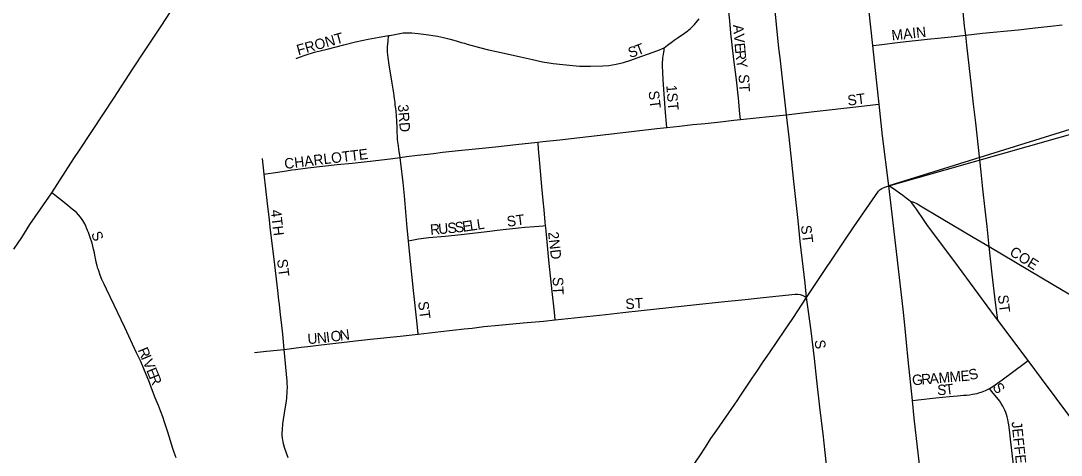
# Model space of a CAD drawing. Extents: x 1772825 to 1773716, y 1138558 to 1139032.
# Drawn here: x 1773337.37 to 1773356.3, y 1138861.97 to 1138869.86 of the extents above; entities that cross this region are included whole.
import ezdxf

# ---------------------------------------------------------------- set-up
doc = ezdxf.new("R2010")
doc.units = 0
for name, color, linetype in [('Default', 7, 'Continuous'), ('GM_X_City_Street', 7, 'Continuous'), ('GM_X_City_Street_Text', 7, 'Continuous'), ('GM_X_State_Route', 7, 'Continuous'), ('SH_Text', 7, 'Continuous')]:
    doc.layers.add(name, color=color, linetype=linetype)

msp = doc.modelspace()

# ---------------------------------------------------------------- linework, layer by layer
at = {"layer": 'Default'}
msp.add_lwpolyline([(1773353.166, 1138866.864), (1773353.051, 1138867.771), (1773352.988, 1138868.345), (1773352.939, 1138868.791), (1773352.873, 1138869.411), (1773352.801, 1138870.079), (1773352.718, 1138870.795), (1773352.633, 1138871.579), (1773352.571, 1138872.151), (1773352.507, 1138872.699), (1773352.374, 1138873.925), (1773352.299, 1138874.578), (1773352.18, 1138875.654), (1773352.138, 1138876.039), (1773352.067, 1138876.669), (1773351.996, 1138877.306)], dxfattribs=at)
at = {"layer": 'GM_X_City_Street'}
for points in [[(1773351.305, 1138868.153), (1773351.299, 1138868.204), (1773351.244, 1138868.698), (1773351.188, 1138869.19), (1773351.167, 1138869.362), (1773351.077, 1138870.226), (1773351.02, 1138870.738), (1773350.917, 1138871.684), (1773350.873, 1138872.052)], [(1773354.565, 1138869.601), (1773354.546, 1138869.763), (1773354.516, 1138870.026), (1773354.442, 1138870.621), (1773354.343, 1138871.551)], [(1773350.466, 1138868.065), (1773350.456, 1138868.17), (1773350.428, 1138868.453), (1773350.391, 1138868.786), (1773350.348, 1138869.157), (1773350.293, 1138869.639), (1773350.272, 1138869.862), (1773350.237, 1138870.195), (1773350.218, 1138870.405), (1773350.194, 1138870.581), (1773350.173, 1138870.711), (1773350.153, 1138870.801), (1773350.128, 1138870.873), (1773350.108, 1138870.918), (1773350.06, 1138871.021)], [(1773349.075, 1138869.371), (1773349.138, 1138869.419), (1773349.229, 1138869.487), (1773349.262, 1138869.51), (1773349.335, 1138869.56), (1773349.447, 1138869.638), (1773349.507, 1138869.682), (1773349.527, 1138869.698), (1773349.554, 1138869.72), (1773349.577, 1138869.742), (1773349.609, 1138869.773), (1773349.629, 1138869.796), (1773349.716, 1138869.9)], [(1773354.565, 1138869.601), (1773354.871, 1138869.634), (1773355.519, 1138869.699), (1773355.883, 1138869.74), (1773356.108, 1138869.765), (1773356.318, 1138869.787)], [(1773342.378, 1138869.179), (1773342.393, 1138869.183), (1773342.401, 1138869.185), (1773342.422, 1138869.193), (1773342.562, 1138869.243), (1773342.716, 1138869.289), (1773342.944, 1138869.347), (1773343.245, 1138869.423), (1773343.462, 1138869.479), (1773343.693, 1138869.528), (1773343.888, 1138869.565), (1773344.06, 1138869.592)], [(1773344.272, 1138867.378), (1773344.249, 1138867.528), (1773344.24, 1138867.589), (1773344.231, 1138867.661), (1773344.226, 1138867.711), (1773344.223, 1138867.758), (1773344.219, 1138867.832), (1773344.216, 1138867.918), (1773344.212, 1138868.043), (1773344.207, 1138868.129), (1773344.199, 1138868.228), (1773344.195, 1138868.265), (1773344.185, 1138868.326), (1773344.18, 1138868.376), (1773344.171, 1138868.449), (1773344.166, 1138868.492), (1773344.157, 1138868.555), (1773344.146, 1138868.619), (1773344.129, 1138868.729), (1773344.073, 1138869.06), (1773344.052, 1138869.194), (1773344.046, 1138869.243), (1773344.043, 1138869.289), (1773344.042, 1138869.326), (1773344.042, 1138869.362), (1773344.043, 1138869.397), (1773344.047, 1138869.434), (1773344.054, 1138869.489), (1773344.057, 1138869.527), (1773344.059, 1138869.553), (1773344.06, 1138869.592)], [(1773344.06, 1138869.592), (1773344.084, 1138869.596), (1773344.266, 1138869.631), (1773344.326, 1138869.641), (1773344.375, 1138869.645), (1773344.487, 1138869.642), (1773344.598, 1138869.633), (1773344.746, 1138869.613), (1773344.954, 1138869.582), (1773345.063, 1138869.56), (1773345.183, 1138869.53), (1773345.29, 1138869.499), (1773345.384, 1138869.469), (1773345.443, 1138869.453), (1773345.49, 1138869.439), (1773345.714, 1138869.377), (1773345.881, 1138869.335), (1773346.026, 1138869.302), (1773346.22, 1138869.259), (1773346.463, 1138869.207), (1773346.681, 1138869.156), (1773346.863, 1138869.118), (1773347.059, 1138869.086), (1773347.231, 1138869.065), (1773347.538, 1138869.039), (1773347.637, 1138869.034), (1773347.736, 1138869.034), (1773347.96, 1138869.041), (1773348.071, 1138869.051), (1773348.206, 1138869.071), (1773348.339, 1138869.104), (1773348.468, 1138869.148), (1773348.584, 1138869.191), (1773348.877, 1138869.292), (1773348.994, 1138869.334), (1773349.05, 1138869.358), (1773349.075, 1138869.371)], [(1773352.873, 1138869.411), (1773352.993, 1138869.425), (1773353.375, 1138869.471), (1773353.872, 1138869.527), (1773354.117, 1138869.552), (1773354.302, 1138869.572), (1773354.565, 1138869.601)], [(1773354.992, 1138865.759), (1773354.953, 1138866.124), (1773354.919, 1138866.429), (1773354.875, 1138866.806), (1773354.845, 1138867.112), (1773354.795, 1138867.557), (1773354.747, 1138868.007), (1773354.705, 1138868.349), (1773354.668, 1138868.682), (1773354.586, 1138869.416), (1773354.565, 1138869.601)], [(1773349.127, 1138867.925), (1773349.122, 1138867.991), (1773349.104, 1138868.195), (1773349.059, 1138868.78), (1773349.051, 1138868.931), (1773349.049, 1138869.028), (1773349.049, 1138869.056), (1773349.05, 1138869.118), (1773349.051, 1138869.144), (1773349.054, 1138869.196), (1773349.057, 1138869.217), (1773349.071, 1138869.289), (1773349.076, 1138869.321), (1773349.077, 1138869.328), (1773349.078, 1138869.333), (1773349.078, 1138869.336), (1773349.078, 1138869.342), (1773349.078, 1138869.347), (1773349.078, 1138869.354), (1773349.077, 1138869.36), (1773349.075, 1138869.371)], [(1773351.305, 1138868.153), (1773351.597, 1138868.187), (1773351.864, 1138868.22), (1773352.568, 1138868.298), (1773352.927, 1138868.338), (1773352.988, 1138868.345)], [(1773349.127, 1138867.925), (1773349.359, 1138867.948), (1773349.599, 1138867.974), (1773349.822, 1138867.996), (1773350.1, 1138868.023), (1773350.343, 1138868.053), (1773350.466, 1138868.065)], [(1773350.466, 1138868.065), (1773350.926, 1138868.114), (1773351.302, 1138868.153), (1773351.305, 1138868.153)], [(1773351.67, 1138864.831), (1773351.641, 1138865.091), (1773351.553, 1138865.849), (1773351.514, 1138866.233), (1773351.44, 1138866.941), (1773351.402, 1138867.294), (1773351.351, 1138867.744), (1773351.305, 1138868.153)], [(1773346.781, 1138867.656), (1773346.871, 1138867.665), (1773347.181, 1138867.698), (1773347.541, 1138867.738), (1773348.174, 1138867.816), (1773348.941, 1138867.902), (1773349.127, 1138867.925)], [(1773344.272, 1138867.378), (1773344.386, 1138867.396), (1773344.59, 1138867.419), (1773344.772, 1138867.439), (1773344.877, 1138867.452), (1773345.042, 1138867.471), (1773345.332, 1138867.504), (1773345.641, 1138867.535), (1773346.007, 1138867.572), (1773346.378, 1138867.615), (1773346.781, 1138867.656)], [(1773346.919, 1138866.141), (1773346.913, 1138866.203), (1773346.893, 1138866.425), (1773346.876, 1138866.596), (1773346.852, 1138866.849), (1773346.8, 1138867.408), (1773346.796, 1138867.454), (1773346.783, 1138867.631), (1773346.781, 1138867.656)], [(1773341.798, 1138867.074), (1773341.766, 1138867.356)], [(1773341.798, 1138867.074), (1773341.828, 1138867.078), (1773342.004, 1138867.106), (1773342.205, 1138867.136), (1773342.302, 1138867.152), (1773342.37, 1138867.161), (1773342.594, 1138867.187), (1773343.126, 1138867.247), (1773343.398, 1138867.276), (1773343.78, 1138867.316), (1773344.138, 1138867.358), (1773344.272, 1138867.378)], [(1773344.423, 1138865.865), (1773344.399, 1138866.097), (1773344.353, 1138866.678), (1773344.33, 1138866.923), (1773344.288, 1138867.272), (1773344.272, 1138867.378)], [(1773342.161, 1138863.889), (1773342.136, 1138864.164), (1773342.111, 1138864.377), (1773342.098, 1138864.516), (1773342.077, 1138864.705), (1773342.067, 1138864.783), (1773342.049, 1138864.959), (1773341.994, 1138865.427), (1773341.909, 1138866.113), (1773341.892, 1138866.243), (1773341.859, 1138866.539), (1773341.798, 1138867.074)], [(1773351.67, 1138864.831), (1773351.804, 1138865.033), (1773352.34, 1138865.84), (1773352.528, 1138866.119), (1773352.814, 1138866.526), (1773352.978, 1138866.765), (1773353.007, 1138866.793), (1773353.038, 1138866.814), (1773353.091, 1138866.84), (1773353.166, 1138866.864)], [(1773340.194, 1138861.916), (1773340.16, 1138862.015), (1773340.137, 1138862.088), (1773340.045, 1138862.386), (1773339.987, 1138862.567), (1773339.956, 1138862.662), (1773339.913, 1138862.772), (1773339.875, 1138862.867), (1773339.851, 1138862.925), (1773339.817, 1138863.012), (1773339.748, 1138863.185), (1773339.711, 1138863.286), (1773339.609, 1138863.537), (1773339.552, 1138863.668), (1773339.473, 1138863.83), (1773339.261, 1138864.289), (1773339.071, 1138864.695), (1773338.927, 1138864.984), (1773338.884, 1138865.073), (1773338.846, 1138865.159), (1773338.815, 1138865.237), (1773338.78, 1138865.333), (1773338.77, 1138865.362), (1773338.757, 1138865.409), (1773338.742, 1138865.477), (1773338.732, 1138865.517), (1773338.722, 1138865.566), (1773338.708, 1138865.646), (1773338.693, 1138865.713), (1773338.665, 1138865.82), (1773338.624, 1138865.942), (1773338.6, 1138866.011), (1773338.584, 1138866.053), (1773338.573, 1138866.082), (1773338.554, 1138866.128), (1773338.533, 1138866.171), (1773338.498, 1138866.229), (1773338.456, 1138866.29), (1773338.416, 1138866.338), (1773338.381, 1138866.375), (1773338.353, 1138866.401), (1773338.329, 1138866.421), (1773338.305, 1138866.441), (1773338.189, 1138866.533), (1773338.074, 1138866.625), (1773338.021, 1138866.669), (1773337.96, 1138866.716), (1773337.932, 1138866.737)], [(1773353.553, 1138866.586), (1773353.602, 1138866.57), (1773353.643, 1138866.554), (1773353.673, 1138866.539), (1773353.711, 1138866.519), (1773354.117, 1138866.276), (1773354.7, 1138865.93), (1773354.992, 1138865.759)], [(1773344.423, 1138865.865), (1773344.606, 1138865.897), (1773344.748, 1138865.916), (1773344.795, 1138865.921), (1773345.091, 1138865.949), (1773345.382, 1138865.976), (1773345.906, 1138866.038), (1773346.04, 1138866.054), (1773346.427, 1138866.096), (1773346.544, 1138866.108), (1773346.718, 1138866.125), (1773346.875, 1138866.138), (1773346.919, 1138866.141)], [(1773347.095, 1138864.427), (1773347.079, 1138864.568), (1773347.037, 1138864.939), (1773346.98, 1138865.509), (1773346.95, 1138865.843), (1773346.922, 1138866.103), (1773346.919, 1138866.141)], [(1773344.603, 1138864.167), (1773344.58, 1138864.356), (1773344.516, 1138864.962), (1773344.465, 1138865.433), (1773344.431, 1138865.787), (1773344.423, 1138865.865)], [(1773354.992, 1138865.759), (1773355.473, 1138865.477), (1773356.178, 1138865.057), (1773356.947, 1138864.604), (1773356.958, 1138864.597)], [(1773355.15, 1138864.422), (1773355.11, 1138864.74), (1773355.045, 1138865.257), (1773354.992, 1138865.759)], [(1773347.095, 1138864.427), (1773348.014, 1138864.524), (1773348.323, 1138864.559), (1773348.656, 1138864.596), (1773349.668, 1138864.705), (1773350.119, 1138864.752), (1773350.551, 1138864.799), (1773350.88, 1138864.832), (1773351.462, 1138864.892), (1773351.512, 1138864.892), (1773351.554, 1138864.888), (1773351.602, 1138864.87), (1773351.638, 1138864.852), (1773351.67, 1138864.831)], [(1773349.484, 1138861.598), (1773349.533, 1138861.671), (1773349.669, 1138861.877), (1773349.725, 1138861.958), (1773349.827, 1138862.113), (1773349.929, 1138862.268), (1773350.034, 1138862.422), (1773350.365, 1138862.895), (1773350.406, 1138862.956), (1773350.458, 1138863.038), (1773350.678, 1138863.367), (1773350.763, 1138863.488), (1773350.879, 1138863.664), (1773350.992, 1138863.827), (1773351.274, 1138864.236), (1773351.42, 1138864.452), (1773351.67, 1138864.831)], [(1773352.099, 1138861.184), (1773352.07, 1138861.453), (1773352.009, 1138862.018), (1773351.973, 1138862.356), (1773351.917, 1138862.787), (1773351.856, 1138863.327), (1773351.811, 1138863.722), (1773351.752, 1138864.224), (1773351.707, 1138864.58), (1773351.67, 1138864.831)], [(1773344.603, 1138864.167), (1773345.016, 1138864.214), (1773345.436, 1138864.261), (1773345.582, 1138864.277), (1773345.794, 1138864.303), (1773346.071, 1138864.332), (1773346.513, 1138864.371), (1773346.879, 1138864.405), (1773347.095, 1138864.427)], [(1773342.161, 1138863.889), (1773342.474, 1138863.929), (1773342.592, 1138863.943), (1773342.836, 1138863.971), (1773343.046, 1138863.996), (1773343.516, 1138864.049), (1773343.735, 1138864.075), (1773344.271, 1138864.131), (1773344.603, 1138864.167)], [(1773341.621, 1138863.832), (1773341.84, 1138863.856), (1773342.161, 1138863.889)], [(1773342.234, 1138861.916), (1773342.17, 1138862.108), (1773342.15, 1138862.175), (1773342.141, 1138862.215), (1773342.137, 1138862.239), (1773342.131, 1138862.277), (1773342.128, 1138862.331), (1773342.127, 1138862.373), (1773342.129, 1138862.429), (1773342.139, 1138862.535), (1773342.182, 1138862.812), (1773342.202, 1138862.947), (1773342.21, 1138863.012), (1773342.219, 1138863.118), (1773342.221, 1138863.213), (1773342.219, 1138863.261), (1773342.216, 1138863.314), (1773342.161, 1138863.889)], [(1773354.999, 1138863.18), (1773355.06, 1138863.218), (1773355.229, 1138863.338), (1773355.627, 1138863.634), (1773355.699, 1138863.688)], [(1773353.595, 1138862.961), (1773353.698, 1138862.973), (1773354.022, 1138863.011), (1773354.145, 1138863.024), (1773354.273, 1138863.036), (1773354.418, 1138863.048), (1773354.525, 1138863.055), (1773354.579, 1138863.058), (1773354.632, 1138863.065), (1773354.69, 1138863.073), (1773354.732, 1138863.081), (1773354.774, 1138863.09), (1773354.807, 1138863.098), (1773354.866, 1138863.118), (1773354.925, 1138863.142), (1773354.999, 1138863.18)], [(1773355.459, 1138861.575), (1773355.439, 1138861.742), (1773355.381, 1138862.258), (1773355.361, 1138862.428), (1773355.348, 1138862.52), (1773355.338, 1138862.576), (1773355.33, 1138862.617), (1773355.32, 1138862.661), (1773355.309, 1138862.704), (1773355.294, 1138862.745), (1773355.279, 1138862.783), (1773355.262, 1138862.821), (1773355.243, 1138862.86), (1773355.212, 1138862.908), (1773355.184, 1138862.949), (1773355.042, 1138863.127), (1773354.999, 1138863.18)]]:
    msp.add_lwpolyline(points, dxfattribs=at)
at = {"layer": 'GM_X_State_Route'}
for points in [[(1773353.166, 1138866.864), (1773353.051, 1138867.771), (1773352.988, 1138868.345), (1773352.939, 1138868.791), (1773352.873, 1138869.411), (1773352.801, 1138870.079), (1773352.718, 1138870.795), (1773352.633, 1138871.579), (1773352.571, 1138872.151), (1773352.56, 1138872.249), (1773352.507, 1138872.699), (1773352.374, 1138873.925)], [(1773337.243, 1138865.71), (1773337.386, 1138865.926), (1773337.536, 1138866.157), (1773337.726, 1138866.44), (1773337.932, 1138866.737), (1773338.278, 1138867.271), (1773338.359, 1138867.394), (1773338.41, 1138867.471), (1773338.672, 1138867.868), (1773338.863, 1138868.153), (1773339.063, 1138868.456), (1773339.406, 1138868.987), (1773339.632, 1138869.325), (1773339.765, 1138869.527), (1773339.921, 1138869.764), (1773340.093, 1138870.023), (1773340.258, 1138870.284), (1773340.327, 1138870.4), (1773340.379, 1138870.487)], [(1773358.016, 1138860.614), (1773357.968, 1138860.678), (1773357.202, 1138861.681), (1773356.814, 1138862.201), (1773356.481, 1138862.648), (1773355.942, 1138863.36), (1773355.699, 1138863.688), (1773355.15, 1138864.422), (1773355.11, 1138864.476), (1773354.35, 1138865.506), (1773353.872, 1138866.139), (1773353.808, 1138866.229), (1773353.668, 1138866.436), (1773353.635, 1138866.486), (1773353.604, 1138866.528), (1773353.579, 1138866.558), (1773353.556, 1138866.583), (1773353.553, 1138866.586), (1773353.484, 1138866.639), (1773353.423, 1138866.684), (1773353.362, 1138866.728), (1773353.293, 1138866.777), (1773353.233, 1138866.818), (1773353.166, 1138866.864)], [(1773353.456, 1138864.329), (1773353.427, 1138864.62), (1773353.225, 1138866.348), (1773353.166, 1138866.864)], [(1773353.949, 1138859.761), (1773353.934, 1138859.896), (1773353.839, 1138860.775), (1773353.77, 1138861.399), (1773353.743, 1138861.637), (1773353.628, 1138862.637), (1773353.595, 1138862.961), (1773353.519, 1138863.702), (1773353.456, 1138864.329)]]:
    msp.add_lwpolyline(points, dxfattribs=at)
at = {"layer": 'SH_Text'}
msp.add_lwpolyline([(1773543.413, 1138925.808), (1773353.166, 1138866.864), (1773543.413, 1138920.862)], close=True, dxfattribs=at)

# ---------------------------------------------------------------- texts
at = {"layer": 'GM_X_City_Street_Text'}
for s, height, rotation, p in [('A', 0.189, 274.5513, (1773350.331, 1138869.786)), ('MAIN', 0.1894, 6.1729, (1773353.225, 1138869.502)), ('FRONT', 0.1894, 15.7855, (1773342.419, 1138869.234)), ('V', 0.189, 274.5754, (1773350.345, 1138869.62)), ('S', 0.189, 17.5105, (1773348.454, 1138869.184)), ('T', 0.189, 21.2091, (1773348.594, 1138869.229)), ('E', 0.189, 274.5663, (1773350.358, 1138869.453)), ('R', 0.189, 275.2807, (1773350.369, 1138869.318)), ('Y', 0.189, 279.2352, (1773350.384, 1138869.154)), ('ST', 0.1894, 273.5882, (1773350.431, 1138868.885)), ('ST', 0.1894, 277.1217, (1773348.791, 1138868.58)), ('1ST', 0.1894, 274.9673, (1773349.115, 1138868.686)), ('ST', 0.1894, 7.1217, (1773352.425, 1138868.318)), ('3RD', 0.1894, 274.4032, (1773344.231, 1138868.336)), ('CHARLOTTE', 0.1894, 6.8698, (1773342.175, 1138867.168)), ('4TH', 0.1894, 276.841, (1773341.915, 1138866.419)), ('ST', 0.1894, 7.12, (1773346.225, 1138866.118)), ('R', 0.189, 5.2274, (1773344.826, 1138865.969)), ('U', 0.189, 5.2083, (1773344.975, 1138865.982)), ('S', 0.189, 5.2073, (1773345.141, 1138865.997)), ('S', 0.189, 6.3213, (1773345.278, 1138866.01)), ('E', 0.189, 8.1133, (1773345.417, 1138866.025)), ('L', 0.189, 8.4264, (1773345.55, 1138866.044)), ('L', 0.189, 8.4513, (1773345.682, 1138866.064)), ('ST', 0.1894, 277.1217, (1773351.564, 1138866.137)), ('S', 0.189, 290.5471, (1773338.646, 1138865.995)), ('2ND', 0.1894, 276.3491, (1773346.965, 1138866.019)), ('COE', 0.1894, 327.9938, (1773355.348, 1138865.613)), ('ST', 0.1894, 277.1217, (1773342.031, 1138865.521)), ('ST', 0.1894, 272.1075, (1773347.048, 1138865.203)), ('ST', 0.1894, 3.5746, (1773348.377, 1138864.619)), ('ST', 0.1894, 277.1217, (1773355.148, 1138864.871)), ('ST', 0.1894, 277.1217, (1773344.598, 1138864.754)), ('I', 0.189, 7.034, (1773342.936, 1138864.016)), ('O', 0.189, 7.1324, (1773343.019, 1138864.026)), ('N', 0.189, 7.1223, (1773343.184, 1138864.047)), ('U', 0.189, 4.1791, (1773342.593, 1138863.985)), ('N', 0.189, 5.9605, (1773342.766, 1138863.998)), ('S', 0.189, 277.1217, (1773351.814, 1138864.054)), ('R', 0.189, 292.5545, (1773339.495, 1138863.88)), ('I', 0.189, 292.5156, (1773339.553, 1138863.741)), ('V', 0.189, 292.5541, (1773339.585, 1138863.664)), ('E', 0.189, 292.5421, (1773339.649, 1138863.51)), ('A', 0.189, 4.7927, (1773353.913, 1138863.262)), ('M', 0.189, 4.8187, (1773354.079, 1138863.276)), ('M', 0.189, 4.8136, (1773354.278, 1138863.293)), ('E', 0.189, 4.8192, (1773354.478, 1138863.309)), ('S', 0.189, 15.1533, (1773354.647, 1138863.327)), ('R', 0.189, 292.6707, (1773339.7, 1138863.387)), ('G', 0.189, 4.8145, (1773353.597, 1138863.235)), ('R', 0.189, 4.8163, (1773353.763, 1138863.249)), ('T', 0.189, 6.7475, (1773354.203, 1138863.062)), ('S', 0.189, 305.5468, (1773355.043, 1138863.202)), ('S', 0.189, 0.3005, (1773354.046, 1138863.06)), ('JEFFERSON', 0.1894, 276.0875, (1773355.398, 1138862.57))]:
    msp.add_text(s, height=height, rotation=rotation, dxfattribs=at).set_placement(p)

doc.saveas('drawing.dxf')
